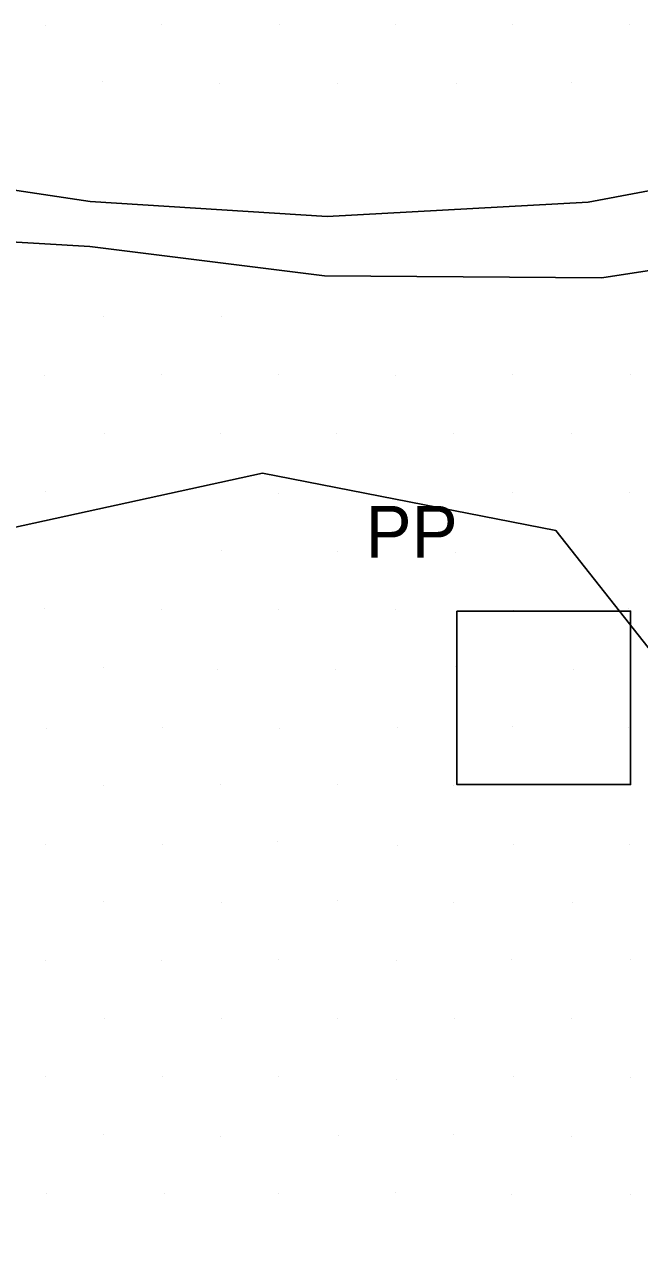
# Model space of a CAD drawing. Extents: x 1602514 to 1609837, y 863887 to 871157.
# Drawn here: x 1605395.4 to 1605469.8, y 866659.7 to 866807.7 of the extents above; entities that cross this region are included whole.
import ezdxf

# ---------------------------------------------------------------- set-up
doc = ezdxf.new("R2010")
doc.units = 0
for name, color, linetype in [('Survey-Ridge Lines', 7, 'Continuous'), ('Survey-Spot dirt', 7, 'Continuous'), ('Survey-Vegetation trees', 7, 'Continuous'), ('Utility-Pole', 7, 'Continuous')]:
    doc.layers.add(name, color=color, linetype=linetype)

msp = doc.modelspace()

# ---------------------------------------------------------------- linework, layer by layer
at = {"layer": 'Survey-Ridge Lines'}
for points in [[(1605271.01, 866733.55), (1605271.13, 866733.84), (1605289.06, 866764.85), (1605290.46, 866799.29), (1605315.08, 866805.27), (1605342.58, 866794.72), (1605372.7, 866790.88), (1605403.41, 866786.28), (1605432.05, 866784.47), (1605463.64, 866786.21), (1605496.91, 866792.44), (1605533.57, 866796.29), (1605572.16, 866793.97)], [(1605271.13, 866733.84), (1605289.06, 866764.85), (1605290.46, 866799.29), (1605315.08, 866805.27), (1605342.58, 866794.72), (1605372.7, 866790.88), (1605403.41, 866786.28), (1605432.05, 866784.47), (1605463.64, 866786.21), (1605496.91, 866792.44), (1605533.57, 866796.29), (1605572.16, 866793.97)], [(1605315.46, 866789.1), (1605342.69, 866785.48), (1605372.69, 866782.64), (1605403.34, 866780.84), (1605431.74, 866777.29), (1605465.29, 866777.04), (1605496.99, 866781.93), (1605532.71, 866782.11), (1605571.74, 866783.81)], [(1605315.46, 866789.1), (1605342.69, 866785.48), (1605372.69, 866782.64), (1605403.34, 866780.84), (1605431.74, 866777.29), (1605465.29, 866777.04), (1605496.99, 866781.93), (1605532.71, 866782.11), (1605571.74, 866783.81)]]:
    msp.add_lwpolyline(points, dxfattribs=at)
at = {"layer": 'Survey-Spot dirt'}
for p, q in [((1605398.01, 866807.63), (1605398.01, 866807.63)), ((1605398.01, 866807.63), (1605398.01, 866807.63)), ((1605412.08, 866807.65), (1605412.08, 866807.65)), ((1605412.08, 866807.65), (1605412.08, 866807.65)), ((1605426.26, 866807.71), (1605426.26, 866807.71)), ((1605426.26, 866807.71), (1605426.26, 866807.71)), ((1605440.38, 866807.67), (1605440.38, 866807.67)), ((1605440.38, 866807.67), (1605440.38, 866807.67)), ((1605454.44, 866807.7), (1605454.44, 866807.7)), ((1605454.44, 866807.7), (1605454.44, 866807.7)), ((1605468.69, 866807.7), (1605468.69, 866807.7)), ((1605468.69, 866807.7), (1605468.69, 866807.7)), ((1605404.94, 866800.75), (1605404.94, 866800.75)), ((1605404.94, 866800.75), (1605404.94, 866800.75)), ((1605419.08, 866800.53), (1605419.08, 866800.53)), ((1605419.08, 866800.53), (1605419.08, 866800.53)), ((1605433.35, 866800.59), (1605433.35, 866800.59)), ((1605433.35, 866800.59), (1605433.35, 866800.59)), ((1605447.66, 866800.55), (1605447.66, 866800.55)), ((1605447.66, 866800.55), (1605447.66, 866800.55)), ((1605461.64, 866800.74), (1605461.64, 866800.74)), ((1605461.64, 866800.74), (1605461.64, 866800.74)), ((1605405.05, 866772.34), (1605405.05, 866772.34)), ((1605405.05, 866772.34), (1605405.05, 866772.34)), ((1605419.25, 866772.37), (1605419.25, 866772.37)), ((1605419.25, 866772.37), (1605419.25, 866772.37)), ((1605412.04, 866765.39), (1605412.04, 866765.39)), ((1605412.04, 866765.39), (1605412.04, 866765.39)), ((1605454.48, 866765.39), (1605454.48, 866765.39)), ((1605454.48, 866765.39), (1605454.48, 866765.39)), ((1605397.93, 866765.2), (1605397.93, 866765.2)), ((1605397.93, 866765.2), (1605397.93, 866765.2)), ((1605426.22, 866765.34), (1605426.22, 866765.34)), ((1605426.22, 866765.34), (1605426.22, 866765.34)), ((1605440.38, 866765.27), (1605440.38, 866765.27)), ((1605440.38, 866765.27), (1605440.38, 866765.27)), ((1605468.73, 866765.33), (1605468.73, 866765.33)), ((1605468.73, 866765.33), (1605468.73, 866765.33)), ((1605405.1, 866758.21), (1605405.1, 866758.21)), ((1605405.1, 866758.21), (1605405.1, 866758.21)), ((1605419.13, 866758.2), (1605419.13, 866758.2)), ((1605419.13, 866758.2), (1605419.13, 866758.2)), ((1605433.25, 866758.22), (1605433.25, 866758.22)), ((1605433.25, 866758.22), (1605433.25, 866758.22)), ((1605447.4, 866758.18), (1605447.4, 866758.18)), ((1605447.4, 866758.18), (1605447.4, 866758.18)), ((1605461.64, 866758.18), (1605461.64, 866758.18)), ((1605461.64, 866758.18), (1605461.64, 866758.18)), ((1605397.96, 866751.16), (1605397.96, 866751.16)), ((1605397.96, 866751.16), (1605397.96, 866751.16)), ((1605412.1, 866751.12), (1605412.1, 866751.12)), ((1605412.1, 866751.12), (1605412.1, 866751.12)), ((1605426.15, 866750.99), (1605426.15, 866750.99)), ((1605426.15, 866750.99), (1605426.15, 866750.99)), ((1605454.48, 866751.09), (1605454.48, 866751.09)), ((1605454.48, 866751.09), (1605454.48, 866751.09)), ((1605468.67, 866751.1), (1605468.67, 866751.1)), ((1605468.67, 866751.1), (1605468.67, 866751.1)), ((1605419.29, 866744.05), (1605419.29, 866744.05)), ((1605419.29, 866744.05), (1605419.29, 866744.05)), ((1605433.35, 866743.89), (1605433.35, 866743.89)), ((1605433.35, 866743.89), (1605433.35, 866743.89)), ((1605447.53, 866743.79), (1605447.53, 866743.79)), ((1605447.53, 866743.79), (1605447.53, 866743.79)), ((1605461.53, 866743.85), (1605461.53, 866743.85)), ((1605461.53, 866743.85), (1605461.53, 866743.85)), ((1605397.84, 866737.04), (1605397.84, 866737.04)), ((1605397.84, 866737.04), (1605397.84, 866737.04)), ((1605412.01, 866736.94), (1605412.01, 866736.94)), ((1605412.01, 866736.94), (1605412.01, 866736.94)), ((1605426.19, 866736.89), (1605426.19, 866736.89)), ((1605426.19, 866736.89), (1605426.19, 866736.89)), ((1605440.32, 866736.93), (1605440.32, 866736.93)), ((1605440.32, 866736.93), (1605440.32, 866736.93)), ((1605454.62, 866736.85), (1605454.62, 866736.85)), ((1605454.62, 866736.85), (1605454.62, 866736.85)), ((1605468.56, 866736.98), (1605468.56, 866736.98)), ((1605468.56, 866736.98), (1605468.56, 866736.98)), ((1605405, 866729.89), (1605405, 866729.89)), ((1605405, 866729.89), (1605405, 866729.89)), ((1605447.55, 866729.96), (1605447.55, 866729.96)), ((1605447.55, 866729.96), (1605447.55, 866729.96)), ((1605418.85, 866729.65), (1605418.85, 866729.65)), ((1605418.85, 866729.65), (1605418.85, 866729.65)), ((1605433.12, 866729.65), (1605433.12, 866729.65)), ((1605433.12, 866729.65), (1605433.12, 866729.65)), ((1605461.87, 866729.63), (1605461.87, 866729.63)), ((1605461.87, 866729.63), (1605461.87, 866729.63)), ((1605398.11, 866722.52), (1605398.11, 866722.52)), ((1605398.11, 866722.52), (1605398.11, 866722.52)), ((1605412.2, 866722.62), (1605412.2, 866722.62)), ((1605412.2, 866722.62), (1605412.2, 866722.62)), ((1605426.25, 866722.57), (1605426.25, 866722.57)), ((1605426.25, 866722.57), (1605426.25, 866722.57)), ((1605440.63, 866722.6), (1605440.63, 866722.6)), ((1605440.63, 866722.6), (1605440.63, 866722.6)), ((1605454.52, 866722.72), (1605454.52, 866722.72)), ((1605454.52, 866722.72), (1605454.52, 866722.72)), ((1605468.57, 866722.67), (1605468.57, 866722.67)), ((1605468.57, 866722.67), (1605468.57, 866722.67)), ((1605404.99, 866715.58), (1605404.99, 866715.58)), ((1605404.99, 866715.58), (1605404.99, 866715.58)), ((1605419.14, 866715.74), (1605419.14, 866715.74)), ((1605419.14, 866715.74), (1605419.14, 866715.74)), ((1605433.31, 866715.76), (1605433.31, 866715.76)), ((1605433.31, 866715.76), (1605433.31, 866715.76)), ((1605447.38, 866715.56), (1605447.38, 866715.56)), ((1605447.38, 866715.56), (1605447.38, 866715.56)), ((1605461.54, 866715.74), (1605461.54, 866715.74)), ((1605461.54, 866715.74), (1605461.54, 866715.74)), ((1605398, 866708.45), (1605398, 866708.45)), ((1605398, 866708.45), (1605398, 866708.45)), ((1605412.1, 866708.51), (1605412.1, 866708.51)), ((1605412.1, 866708.51), (1605412.1, 866708.51)), ((1605426.08, 866708.82), (1605426.08, 866708.82)), ((1605426.08, 866708.82), (1605426.08, 866708.82)), ((1605440.57, 866708.35), (1605440.57, 866708.35)), ((1605440.57, 866708.35), (1605440.57, 866708.35)), ((1605454.57, 866708.49), (1605454.57, 866708.49)), ((1605454.57, 866708.49), (1605454.57, 866708.49)), ((1605468.59, 866708.54), (1605468.59, 866708.54)), ((1605468.59, 866708.54), (1605468.59, 866708.54)), ((1605433.34, 866701.72), (1605433.34, 866701.72)), ((1605433.34, 866701.72), (1605433.34, 866701.72)), ((1605405.06, 866701.64), (1605405.06, 866701.64)), ((1605405.06, 866701.64), (1605405.06, 866701.64)), ((1605419.27, 866701.51), (1605419.27, 866701.51)), ((1605419.27, 866701.51), (1605419.27, 866701.51)), ((1605447.35, 866701.52), (1605447.35, 866701.52)), ((1605447.35, 866701.52), (1605447.35, 866701.52)), ((1605461.68, 866701.52), (1605461.68, 866701.52)), ((1605461.68, 866701.52), (1605461.68, 866701.52)), ((1605398.01, 866694.42), (1605398.01, 866694.42)), ((1605398.01, 866694.42), (1605398.01, 866694.42)), ((1605412.05, 866694.48), (1605412.05, 866694.48)), ((1605412.05, 866694.48), (1605412.05, 866694.48)), ((1605426.16, 866694.59), (1605426.16, 866694.59)), ((1605426.16, 866694.59), (1605426.16, 866694.59)), ((1605440.4, 866694.5), (1605440.4, 866694.5)), ((1605440.4, 866694.5), (1605440.4, 866694.5)), ((1605454.38, 866694.54), (1605454.38, 866694.54)), ((1605454.38, 866694.54), (1605454.38, 866694.54)), ((1605468.74, 866694.56), (1605468.74, 866694.56)), ((1605468.74, 866694.56), (1605468.74, 866694.56)), ((1605405.14, 866687.38), (1605405.14, 866687.38)), ((1605405.14, 866687.38), (1605405.14, 866687.38)), ((1605419.24, 866687.46), (1605419.24, 866687.46)), ((1605419.24, 866687.46), (1605419.24, 866687.46)), ((1605433.32, 866687.44), (1605433.32, 866687.44)), ((1605433.32, 866687.44), (1605433.32, 866687.44)), ((1605447.47, 866687.38), (1605447.47, 866687.38)), ((1605447.47, 866687.38), (1605447.47, 866687.38)), ((1605461.56, 866687.42), (1605461.56, 866687.42)), ((1605461.56, 866687.42), (1605461.56, 866687.42)), ((1605398.01, 866680.37), (1605398.01, 866680.37)), ((1605398.01, 866680.37), (1605398.01, 866680.37)), ((1605412.1, 866680.36), (1605412.1, 866680.36)), ((1605412.1, 866680.36), (1605412.1, 866680.36)), ((1605426.14, 866680.46), (1605426.14, 866680.46)), ((1605426.14, 866680.46), (1605426.14, 866680.46)), ((1605440.39, 866680.02), (1605440.39, 866680.02)), ((1605440.39, 866680.02), (1605440.39, 866680.02)), ((1605454.56, 866680.37), (1605454.56, 866680.37)), ((1605454.56, 866680.37), (1605454.56, 866680.37)), ((1605468.78, 866680.28), (1605468.78, 866680.28)), ((1605468.78, 866680.28), (1605468.78, 866680.28)), ((1605405.02, 866673.35), (1605405.02, 866673.35)), ((1605405.02, 866673.35), (1605405.02, 866673.35)), ((1605419.21, 866673.18), (1605419.21, 866673.18)), ((1605419.21, 866673.18), (1605419.21, 866673.18)), ((1605433.41, 866673.32), (1605433.41, 866673.32)), ((1605433.41, 866673.32), (1605433.41, 866673.32)), ((1605447.39, 866673.42), (1605447.39, 866673.42)), ((1605447.39, 866673.42), (1605447.39, 866673.42)), ((1605461.56, 866673.12), (1605461.56, 866673.12)), ((1605461.56, 866673.12), (1605461.56, 866673.12)), ((1605398.11, 866666.31), (1605398.11, 866666.31)), ((1605398.11, 866666.31), (1605398.11, 866666.31)), ((1605412.35, 866666.21), (1605412.35, 866666.21)), ((1605412.35, 866666.21), (1605412.35, 866666.21)), ((1605426.2, 866666.29), (1605426.2, 866666.29)), ((1605426.2, 866666.29), (1605426.2, 866666.29)), ((1605440.31, 866666.36), (1605440.31, 866666.36)), ((1605440.31, 866666.36), (1605440.31, 866666.36)), ((1605454.37, 866666.1), (1605454.37, 866666.1)), ((1605454.37, 866666.1), (1605454.37, 866666.1)), ((1605468.76, 866666.1), (1605468.76, 866666.1)), ((1605468.76, 866666.1), (1605468.76, 866666.1))]:
    msp.add_line(p, q, dxfattribs=at)
at = {"layer": 'Survey-Vegetation trees'}
msp.add_lwpolyline([(1605601.79, 866275.83), (1605605.2, 866448.65), (1605612.42, 866530.39), (1605609.93, 866556.1), (1605459.73, 866746.47), (1605424.26, 866753.41), (1605387.87, 866745.45), (1605328.37, 866764.72), (1605298.66, 866722.79), (1605306.28, 866699.16), (1605277.32, 866658.75), (1605265.13, 866625.97), (1605217.79, 866602.88), (1605158.36, 866628.8), (1605148.45, 866592.97), (1605247.5, 866507.58), (1605323.27, 866431.24), (1605384.81, 866367.9), (1605438.61, 866328.19), (1605473.87, 866349.1), (1605499.88, 866323.66)], dxfattribs=at)
msp.add_lwpolyline([(1605601.79, 866275.83), (1605605.2, 866448.65), (1605612.42, 866530.39), (1605609.93, 866556.1), (1605459.73, 866746.47), (1605424.26, 866753.41), (1605387.87, 866745.45), (1605328.37, 866764.72), (1605298.66, 866722.79), (1605306.28, 866699.16), (1605277.32, 866658.75), (1605265.13, 866625.97), (1605217.79, 866602.88), (1605158.36, 866628.8), (1605148.45, 866592.97), (1605247.5, 866507.58), (1605323.27, 866431.24), (1605384.81, 866367.9), (1605438.61, 866328.19), (1605473.87, 866349.1), (1605499.88, 866323.66)], dxfattribs=at)
at = {"layer": 'Utility-Pole'}
msp.add_lwpolyline([(1605447.75, 866736.73), (1605468.76, 866736.73), (1605468.76, 866715.73), (1605447.75, 866715.73)], close=True, dxfattribs=at)
msp.add_lwpolyline([(1605447.75, 866736.73), (1605468.76, 866736.73), (1605468.76, 866715.73), (1605447.75, 866715.73)], close=True, dxfattribs=at)

# ---------------------------------------------------------------- texts
msp.add_text('PP', height=6.251, dxfattribs=at).set_placement((1605436.7, 866743.2))
msp.add_text('PP', height=6.251, dxfattribs=at).set_placement((1605436.7, 866743.2))

doc.saveas('drawing.dxf')
